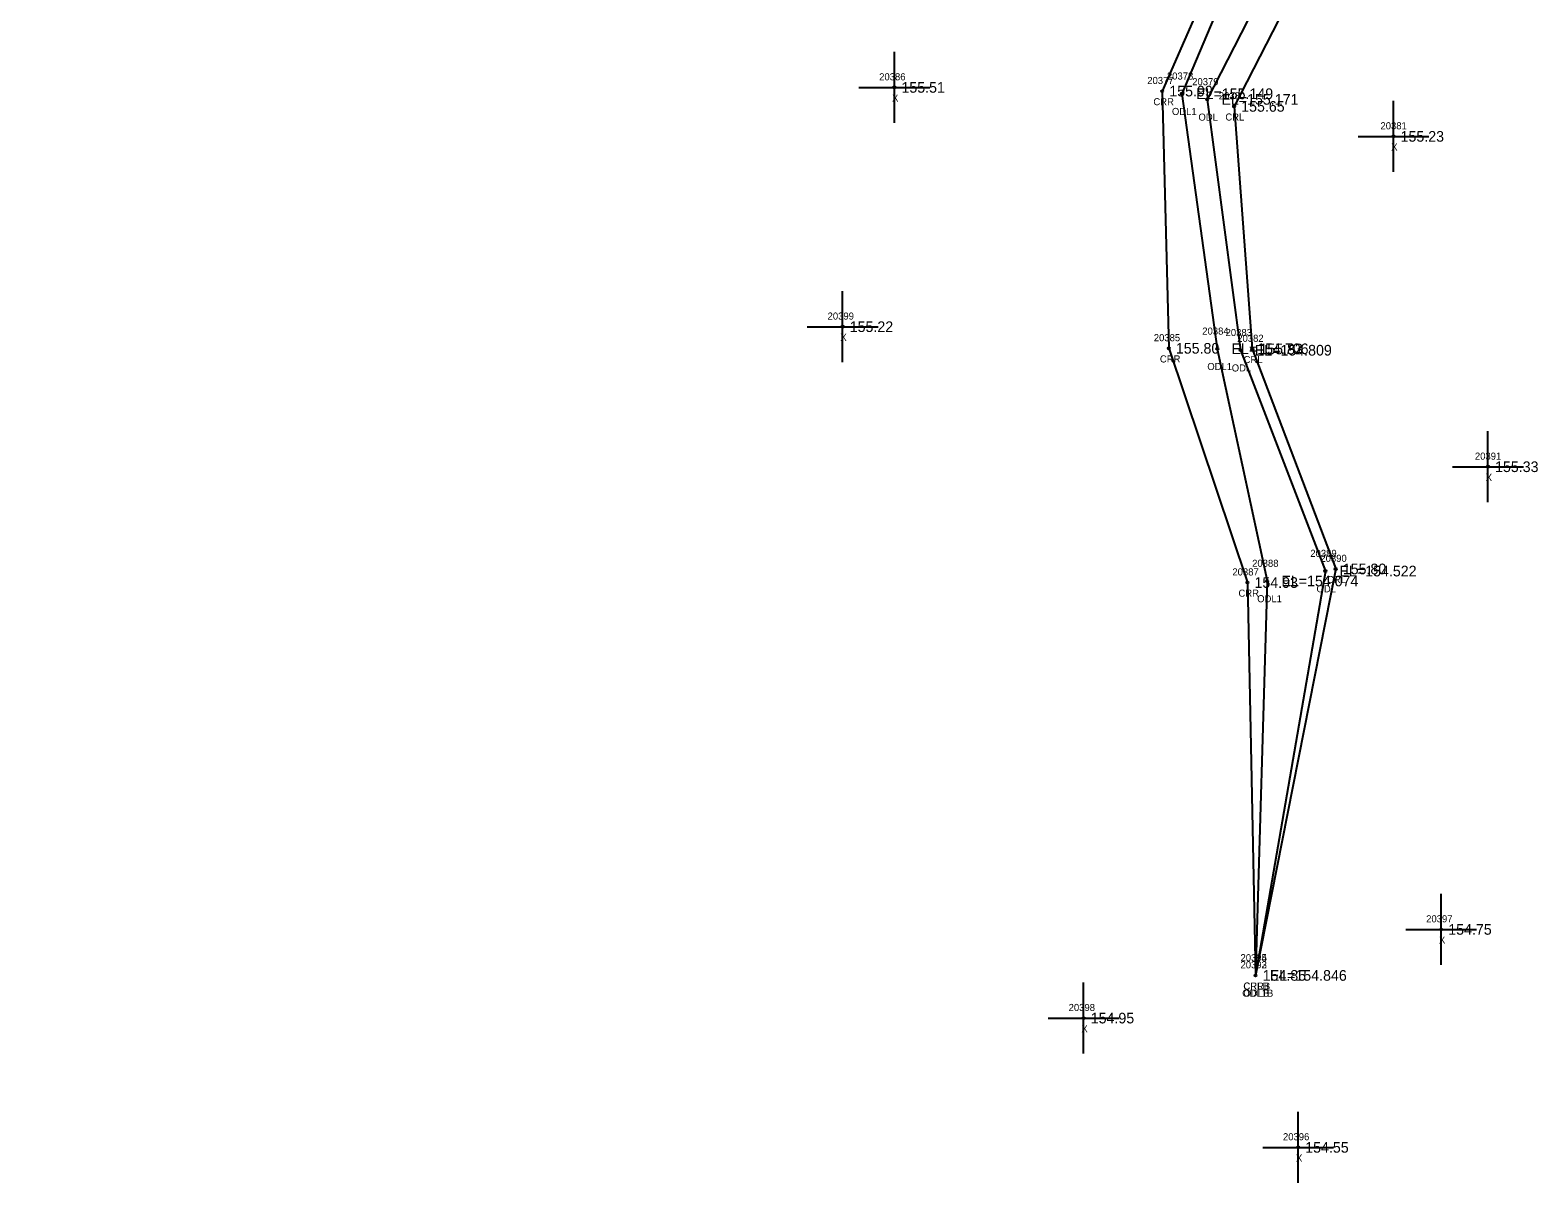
# Model space of a CAD drawing. Extents: x 2381545 to 2382928, y 1029933 to 1030589.
# Drawn here: x 2382160.7 to 2382373.5, y 1029932.7 to 1030095.3 of the extents above; entities that cross this region are included whole.
import ezdxf

# ---------------------------------------------------------------- set-up
doc = ezdxf.new("R2010")
doc.units = 0
for name, color, linetype in [('RD_EX_H2O', 7, 'Continuous'), ('RD_EX_H2O_txCode', 7, 'Continuous'), ('RD_EX_Misc', 7, 'Continuous'), ('RD_EX_Misc_txCode', 7, 'Continuous'), ('RD_EX_TX_H2O_ELEV', 7, 'Continuous'), ('RD_EX_TX_Misc_ELEV', 7, 'Continuous'), ('RD_SMD_Locator', 7, 'Continuous')]:
    doc.layers.add(name, color=color, linetype=linetype)

msp = doc.modelspace()

# ---------------------------------------------------------------- linework, layer by layer
at = {"layer": 'RD_EX_H2O'}
for points in [[(2382228.76, 1030407.08), (2382229.33, 1030393.42), (2382229.44, 1030376.02), (2382235.1, 1030355.5), (2382240.51, 1030349.49), (2382245.56, 1030316.86), (2382248.97, 1030289.05), (2382238.04, 1030280.56), (2382242.49, 1030255.05), (2382259.38, 1030214.05), (2382335.14, 1030213.97), (2382351.43, 1030124.97), (2382330.65, 1030084.53), (2382333.22, 1030050.31), (2382344.99, 1030019.27), (2382333.68, 1029961.92)], [(2382160.73, 1030399.39), (2382197.66, 1030393.98), (2382201.16, 1030391.22), (2382207.75, 1030374.4), (2382216.83, 1030343.34), (2382214.66, 1030277.58), (2382224.95, 1030248.16), (2382253.35, 1030190.66), (2382280.97, 1030189.84), (2382308.61, 1030179.94), (2382336.27, 1030122.7), (2382320.51, 1030086.69), (2382321.43, 1030050.4), (2382332.53, 1030017.35), (2382333.68, 1029961.92)], [(2382213.26, 1030387.6), (2382221.81, 1030359.48), (2382223.97, 1030346.38), (2382221.92, 1030320.69), (2382220.3, 1030284.96), (2382227.77, 1030249.4), (2382256.92, 1030199.53), (2382280.94, 1030192.97), (2382312.22, 1030183.5), (2382338.65, 1030122.69), (2382323.29, 1030086.32), (2382328.28, 1030050.33), (2382335.32, 1030017.57), (2382333.68, 1029961.92)], [(2382220.88, 1030388.74), (2382227.06, 1030360.93), (2382229.81, 1030345.11), (2382235.02, 1030321.93), (2382245.69, 1030289.44), (2382231.02, 1030286.27), (2382239.27, 1030255.62), (2382259.54, 1030209.53), (2382328.62, 1030208.08), (2382346.92, 1030124.75), (2382326.86, 1030085.52), (2382331.57, 1030050.13), (2382343.53, 1030018.97), (2382333.68, 1029961.92)]]:
    msp.add_lwpolyline(points, dxfattribs=at)
at = {"layer": 'RD_EX_Misc'}
for p, q in [((2382282.7, 1030082.21), (2382282.7, 1030092.21)), ((2382277.7, 1030087.21), (2382287.7, 1030087.21)), ((2382353.15, 1030075.3), (2382353.15, 1030085.3)), ((2382348.15, 1030080.3), (2382358.15, 1030080.3)), ((2382275.4, 1030048.45), (2382275.4, 1030058.45)), ((2382270.4, 1030053.45), (2382280.4, 1030053.45)), ((2382366.48, 1030028.69), (2382366.48, 1030038.69)), ((2382361.48, 1030033.69), (2382371.48, 1030033.69)), ((2382359.88, 1029963.41), (2382359.88, 1029973.41)), ((2382354.88, 1029968.41), (2382364.88, 1029968.41)), ((2382309.42, 1029950.9), (2382309.42, 1029960.9)), ((2382304.42, 1029955.9), (2382314.42, 1029955.9)), ((2382339.69, 1029932.66), (2382339.69, 1029942.66)), ((2382334.69, 1029937.66), (2382344.69, 1029937.66))]:
    msp.add_line(p, q, dxfattribs=at)
at = {"layer": 'RD_SMD_Locator'}
for centre in [(2382282.7, 1030087.21), (2382320.51, 1030086.69), (2382323.29, 1030086.32), (2382326.86, 1030085.52), (2382330.65, 1030084.53), (2382353.15, 1030080.3), (2382275.4, 1030053.45), (2382321.43, 1030050.4), (2382328.28, 1030050.33), (2382331.57, 1030050.13), (2382333.22, 1030050.31), (2382366.48, 1030033.69), (2382344.99, 1030019.27), (2382332.53, 1030017.35), (2382335.32, 1030017.57), (2382343.53, 1030018.97), (2382359.88, 1029968.41), (2382333.68, 1029961.92), (2382333.68, 1029961.92), (2382333.68, 1029961.92), (2382333.68, 1029961.92), (2382309.42, 1029955.9), (2382339.69, 1029937.66)]:
    msp.add_circle(centre, 0.15, dxfattribs=at)

# ---------------------------------------------------------------- texts
at = {"layer": 'RD_EX_H2O_txCode'}
for s, p in [('20377', (2382318.4, 1030087.69)), ('20378', (2382321.17, 1030088.32)), ('20379', (2382324.74, 1030087.52)), ('CRR', (2382319.26, 1030084.69)), ('20380', (2382328.49, 1030085.53)), ('ODL1', (2382321.88, 1030083.32)), ('ODL', (2382325.62, 1030082.52)), ('CRL', (2382329.42, 1030082.53)), ('20385', (2382319.32, 1030051.4)), ('20384', (2382326.16, 1030052.33)), ('20383', (2382329.45, 1030052.13)), ('20382', (2382331.1, 1030051.31)), ('CRR', (2382320.18, 1030048.4)), ('CRL', (2382331.99, 1030048.31)), ('ODL1', (2382326.87, 1030047.33)), ('ODL', (2382330.32, 1030047.13)), ('20389', (2382341.41, 1030020.97)), ('20387', (2382330.41, 1030018.35)), ('20388', (2382333.2, 1030019.57)), ('20390', (2382342.83, 1030020.27)), ('CRL', (2382343.76, 1030017.27)), ('CRR', (2382331.27, 1030015.35)), ('ODL1', (2382333.91, 1030014.57)), ('ODL', (2382342.28, 1030015.97)), ('20394', (2382331.56, 1029963.92)), ('20395', (2382331.56, 1029963.92)), ('20392', (2382331.56, 1029962.92)), ('20393', (2382331.56, 1029962.92)), ('ODL1B', (2382331.8, 1029958.92)), ('CRRB', (2382331.95, 1029959.92)), ('ODLB', (2382331.96, 1029958.92)), ('CRLB', (2382331.98, 1029959.92))]:
    msp.add_text(s, height=1, dxfattribs=at).set_placement(p)
at = {"layer": 'RD_EX_Misc_txCode'}
for s, p in [('20386', (2382280.56, 1030088.21)), ('X', (2382282.38, 1030085.21)), ('20381', (2382351.31, 1030081.3)), ('X', (2382352.83, 1030078.3)), ('20399', (2382273.28, 1030054.45)), ('X', (2382275.08, 1030051.45)), ('20391', (2382364.64, 1030034.69)), ('X', (2382366.16, 1030031.69)), ('20397', (2382357.76, 1029969.41)), ('X', (2382359.57, 1029966.41)), ('20398', (2382307.3, 1029956.9)), ('X', (2382309.1, 1029953.9)), ('20396', (2382337.55, 1029938.66)), ('X', (2382339.38, 1029935.66))]:
    msp.add_text(s, height=1, dxfattribs=at).set_placement(p)
at = {"layer": 'RD_EX_TX_H2O_ELEV'}
for s, p in [('155.99', (2382321.51, 1030085.94)), ('EL=155.149', (2382325.29, 1030085.57)), ('EL=155.171', (2382328.86, 1030084.77)), ('155.65', (2382331.65, 1030083.78)), ('155.80', (2382322.43, 1030049.65)), ('EL=154.706', (2382330.28, 1030049.58)), ('EL=154.809', (2382333.57, 1030049.38)), ('155.83', (2382334.22, 1030049.56)), ('EL=154.522', (2382345.53, 1030018.22)), ('155.80', (2382345.99, 1030018.52)), ('154.93', (2382333.53, 1030016.6)), ('EL=154.074', (2382337.32, 1030016.82)), ('154.85', (2382334.68, 1029961.17)), ('154.85', (2382334.68, 1029961.17)), ('EL=154.846', (2382335.68, 1029961.17)), ('EL=154.846', (2382335.68, 1029961.17))]:
    msp.add_text(s, height=1.5, dxfattribs=at).set_placement(p)
at = {"layer": 'RD_EX_TX_Misc_ELEV'}
for s, p in [('155.51', (2382283.7, 1030086.46)), ('155.23', (2382354.15, 1030079.55)), ('155.22', (2382276.4, 1030052.7)), ('155.33', (2382367.48, 1030032.94)), ('154.75', (2382360.88, 1029967.66)), ('154.95', (2382310.42, 1029955.15)), ('154.55', (2382340.69, 1029936.91))]:
    msp.add_text(s, height=1.5, dxfattribs=at).set_placement(p)

doc.saveas('drawing.dxf')
